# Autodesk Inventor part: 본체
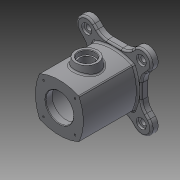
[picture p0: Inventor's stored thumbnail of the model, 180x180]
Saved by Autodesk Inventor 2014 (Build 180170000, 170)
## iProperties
Created: 2016-05
Part Number: 본체
Material: 일반
Document SubType Name: Modeling
Designer: Administrator
Density: 1 g/cm^3
Appearance: 기본값
Author: Administrator
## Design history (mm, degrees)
sketch "스케치1"
  geometry: L1 (-35.355, -35.355)-(35.355, -35.355); L2 (35.355, -35.355)-(35.355, 35.355); L3 (35.355, 35.355)-(-35.355, 35.355); L4 (-35.355, 35.355)-(-35.355, -35.355); L5 (-35.355, -35.355)-(35.355, 35.355); L6 (35.355, -35.355)-(-35.355, 35.355); A1 r 85.579 centre (0, -42.579) between (35.355, 35.355) and (-35.355, 35.355); A2 r 85.579 centre (42.579, 0) between (-35.355, 35.355) and (-35.355, -35.355); A3 r 85.579 centre (0, 42.579) between (-35.355, -35.355) and (35.355, -35.355); A4 r 85.579 centre (-42.579, 0) between (35.355, -35.355) and (35.355, 35.355); 1 further point
  constraints: 12 end point, 8 point on circle, 4 centre point, 3 equal radius, 2 midpoint, 2 parallel, 1 horizontal, 1 perpendicular
  dimensions: "d0" = 100 distance of L1.start L2.end; "d1" = 100 distance of L1.end L3.end (derived); "d2" = 86 dimension on A3 A1; "d3" = 86 dimension on A2 A4
extrude "돌출1" new body sketch "스케치1" distance "d4" = 49; taper "d5" = 0 deg
sketch "스케치3"
  geometry: 1 further point
hole "구멍1" sketch "스케치3" at (0, 0) diameter "d14" = 50; stored, may be unused: countersink angle "d18" = 90 deg, drill point angle "d20" = 118 deg; dims "d15" = 6, "d16" = 70, "d17" = 49, "d19" = 8
sketch "스케치4"
  geometry: 1 further point
hole "구멍2" sketch "스케치4" at (0, 0) diameter "d21" = 50; stored, may be unused: countersink angle "d25" = 90 deg, drill point angle "d27" = 118 deg; dims "d22" = 6, "d23" = 70, "d24" = 37, "d26" = 8
sketch "스케치2"
  geometry: L1 (49.497, -49.497)-(-49.497, 49.497); L2 (49.497, 49.497)-(-49.497, -49.497); L3 (0, 98)-(0, -98) reference; L4 (-49, 49)-(49, 49); L5 (49, 49)-(49, -49); L6 (49, -49)-(-49, -49); L7 (-49, -49)-(-49, 49); L8 (-49, 49)-(49, -49); L9 (49, 49)-(-49, -49); L10 (62.225, -36.77)-(49, -23.544); L11 (36.77, -62.225)-(23.544, -49); L12 (-36.77, -62.225)-(-23.544, -49); L13 (-62.225, -36.77)-(-49, -23.544); L14 (-60.483, 35.239)-(-49, 26.391); L15 (-36.77, 62.225)-(-23.544, 49); L16 (36.77, 62.225)-(23.544, 49); L17 (62.225, 36.77)-(49, 23.544); A1 r 70 centre (0, 0) between (-49.497, -49.497) and (49.497, -49.497); A2 r 18 centre (49.497, -49.497) between (62.225, -36.77) and (36.77, -62.225); A3 r 18 centre (-49.497, -49.497) between (-36.77, -62.225) and (-62.225, -36.77); A4 r 18 centre (-49.497, 49.497) between (-60.483, 35.239) and (-36.77, 62.225); A5 r 18 centre (49.497, 49.497) between (36.77, 62.225) and (62.225, 36.77); 3 further points
  constraints: 32 end point, 12 point on circle, 11 point on line, 8 tangent, 7 parallel, 5 centre point, 5 coincident, 4 midpoint, 3 equal radius, 3 perpendicular, 1 horizontal
  dimensions: "d6" = 70 radius of A1; "d7" = 45 deg angle of L3 L2; "d8" = 45 deg angle of L1 L3; "d10" = 18 radius of A2; "d11" = 98 distance of L5.end L6.end
extrude "돌출2" join sketch "스케치2" distance "d12" = 12; taper "d13" = 0 deg
sketch "스케치5"
  geometry: 1 further point
hole "구멍3" sketch "스케치5" at (0, 0) diameter "d28" = 50; stored, may be unused: countersink angle "d32" = 90 deg, drill point angle "d34" = 118 deg; dims "d29" = 6, "d30" = 70, "d31" = 37, "d33" = 8
node "작업 평면1"
sketch "스케치6"
  geometry: C1 r 20 at (0, 0); 1 further point
  constraints: 1 centre point, 1 coincident
  dimensions: "d37" = 40 diameter of C1
extrude "돌출3" join sketch "스케치6" stored distance "d38" = 12; taper "d39" = 10 deg
sketch "스케치7"
  geometry: 1 further point
hole "구멍5" sketch "스케치7" at (0, 0) diameter "d49" = 25; stored, may be unused: countersink angle "d53" = 90 deg, drill point angle "d55" = 118 deg; dims "d50" = 6, "d51" = 30, "d52" = 8, "d54" = 8
sketch "스케치8"
  geometry: L1 (0, 42.579)-(-28.284, 70.863); L2 (0, -51.918)-(0, 137.075) reference
  constraints: 2 end point
  dimensions: "d56" = 45 deg angle of L2 L1; "d57" = 40 distance of L1.start L1.end
hole "구멍6" sketch "스케치8" at (-28.284, 70.863) diameter "d58" = 3.242; stored, may be unused: countersink angle "d62" = 90 deg, drill point angle "d64" = 118 deg; dims "d59" = 7, "d60" = 30, "d61" = 8, "d63" = 10
sketch "스케치10"
  geometry: L1 (49, -49)-(-49, -49); L2 (-49, -49)-(-49, 49); L3 (-49, 49)-(49, 49); L4 (49, 49)-(49, -49); L5 (49, -49)-(-49, 49); L6 (-49, -49)-(49, 49); 1 further point
  constraints: 12 end point, 2 midpoint, 2 parallel, 2 perpendicular, 1 horizontal
  dimensions: "d77" = 98 distance of L2.end L3.end; "d78" = 98 distance of L1.end L2.end (derived)
hole "구멍8" sketch "스케치10" at (-49, 49) diameter "d79" = 10; stored, may be unused: countersink angle "d83" = 90 deg, drill point angle "d85" = 118 deg; dims "d80" = 7, "d81" = 18, "d82" = 4, "d84" = 10
fillet "모깎기1" dims "d92" = 3
fillet "모깎기2" dims "d93" = 3
fillet "모깎기3" dims "d94" = 25
fillet "모깎기4" dims "d95" = 3
chamfer "모따기1" distance "d96" = 1; stored, may be unused: second distance "d97" = 2, angle "d98" = 45 deg
fillet "모깎기5" dims "d99" = 3
fillet "모깎기6" dims "d100" = 3
sketch "스케치11"
  geometry: L1 (0, 0)-(28.284, -28.284); L2 (0, 94.496)-(0, -94.496) reference
  constraints: 2 end point
  dimensions: "d101" = 45 deg angle of L2 L1; "d102" = 40 distance of L1.start L1.end
hole "구멍9" sketch "스케치11" at (28.284, -28.284) diameter "d103" = 3.242; stored, may be unused: countersink angle "d107" = 90 deg, drill point angle "d109" = 118 deg; dims "d104" = 7, "d105" = 18, "d106" = 4, "d108" = 10
node "솔리드1"
mirror "대칭1"
pattern_circular "원형 패턴1" dims angle "d66" = 360 deg
pattern_linear "직사각형 패턴1" dims "d88" = 98 (= d77), "d91" = 98 (= d78)
pattern_circular "원형 패턴2" dims angle "d111" = 360 deg
other parameters: "d35" = 55
